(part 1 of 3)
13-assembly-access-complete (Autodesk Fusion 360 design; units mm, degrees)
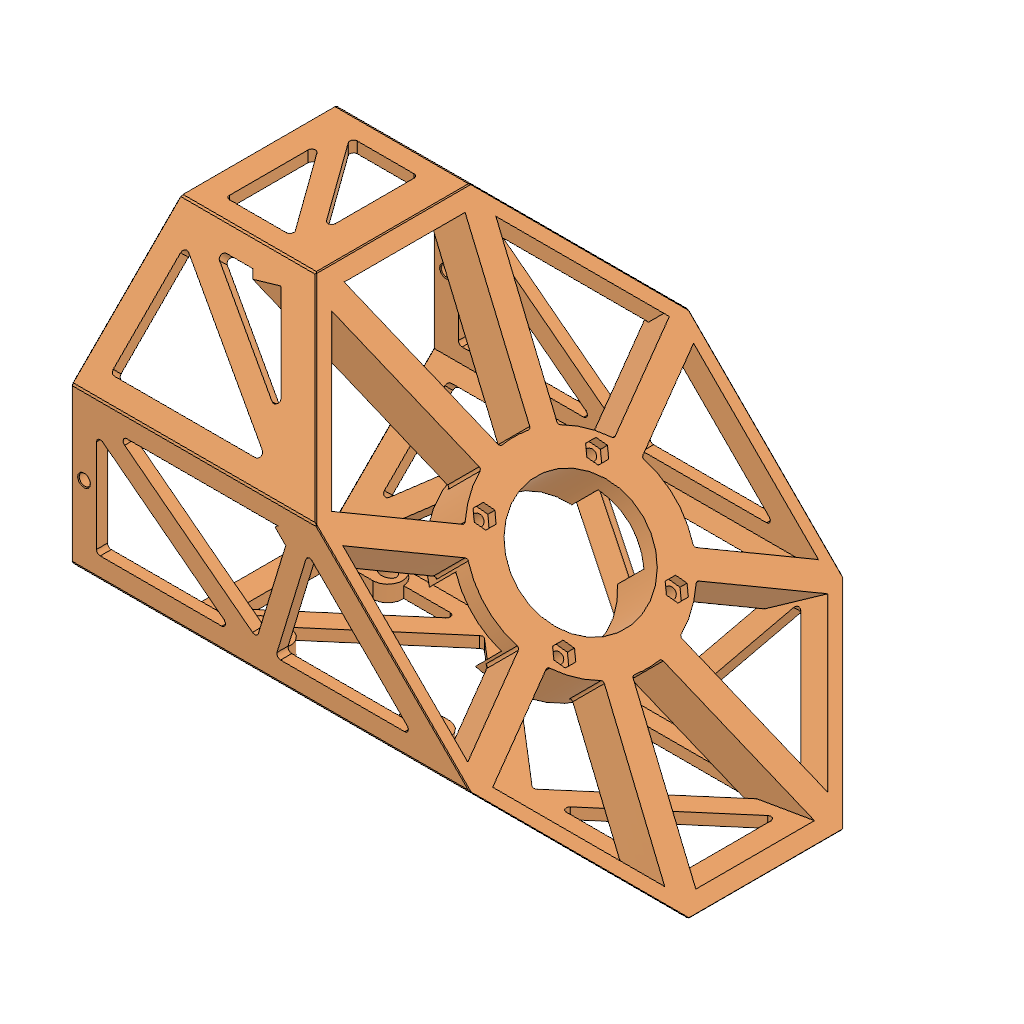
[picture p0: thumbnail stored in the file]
part number: 2026-11-02-20-17-55-344
part number: 2026-11-02-20-17-59-218
part number: 2026-11-02-20-17-59-224
part number: 2026-11-02-20-19-00-695
part number: 2026-11-02-20-19-03-009
part number: 2026-11-02-20-19-04-949
part number: 2026-11-02-20-19-06-912
part number: 2026-11-02-20-19-11-903
part number: 2026-11-02-20-19-12-666
part number: 2026-11-02-20-19-12-978
part number: 2026-11-02-20-19-13-740
part number: 2026-11-02-20-19-14-532
part number: 2026-11-02-20-19-15-361
part number: 2026-11-02-20-19-17-468
part number: 2026-11-02-20-19-19-583
part number: 2026-11-02-20-19-25-638
part number: 2026-11-02-20-19-39-091
parameter "bodyWidth" = 150 comment "Regular octagon across flats; corner diameter is larger."
parameter "bodyLength" = 260 comment "Overall straight length of the shared master blank."
parameter "splitAngle" = 45 comment "Keep this lesson angle at45 degrees."
parameter "faceGap" = 1 comment "Gap between the two printed joint faces."
parameter "wall" = 4.5 comment "Integrated shell and side brace radial thickness."
parameter "faceHalfWidth" = 31.066 (= "bodyWidth * ( sqrt(2) - 1 ) / 2") comment "Half-width of each outer planar facet."
parameter "memberWidth" = 8 comment "Nominal brace and corner chord width in a facet."
parameter "nodeHalfWidth" = 27.066 (= "faceHalfWidth - memberWidth / 2") comment "Chord centerlines measured from facet center."
parameter "jointNodeQ" = 7 comment "First truss skeleton row from the center joint plane."
parameter "endRim" = 10 comment "Uncut axial rim at each distant end."
parameter "endNodeX" = 124 (= "bodyLength / 2 - endRim + memberWidth / 2") comment "Last skeleton row before aperture inset."
parameter "apertureRadius" = 1.5 comment "Rounded internal corners at triangular openings."
parameter "spokeWidth" = 10 comment "Width of each deep bearing bulkhead spoke."
parameter "spokeDepth" = 18 comment "Bulkhead depth normal to the diagonal joint face."
parameter "carrierOD" = 52 comment "Outside of integrated A front bearing carrier."
parameter "rearCarrierClearance" = 46 comment "Internal carrier relief above front bearing shoulder."
parameter "tubeCornerChamfer" = 0.5 comment "Exposed outside octagon corner bevel."
parameter "tubeRimChamfer" = 0.3 comment "End rim and print-contact edge relief."
parameter "cordStation" = 125 (= "bodyLength / 2 - endRim / 2") comment "Load-test cord port center measured along body X."
parameter "bearingOD" = 22 comment "608 measured outside diameter."
parameter "bearingID" = 8 comment "608 bore."
parameter "bearingWidth" = 7 comment "608 width."
parameter "seatAllowance" = 0.2 comment "Trial DIAMETRAL clearance; choose with printed coupon."
parameter "seatDiameter" = 22.2 (= "bearingOD + seatAllowance") comment "Measured fit controls this."
parameter "coreOD" = 44 comment "Bearing holder outer diameter."
parameter "raceRelief" = 19.5 comment "Outer-ring shoulder opening; verify seals."
parameter "frontSeatDepth" = 7.1 comment "0.1 mm outer-ring axial allowance."
parameter "rearSeatDepth" = 7.2 comment "0.2 mm outer-ring axial float."
parameter "shoulder" = 3 comment "Backing behind each bearing seat."
parameter "supportSpacer" = 12 comment "Purchased metal M3 spacer length."
parameter "supportCircle" = 34 comment "Three M3 support bolts."
parameter "supportSpacerOD" = 6 comment "Purchased spacer outside diameter."
parameter "capThickness" = 3 comment "Both printed outer-ring retaining caps."
parameter "m3Clearance" = 3.3 comment "M3 through holes."
parameter "m4Clearance" = 4.3 comment "M4 through holes."
parameter "qFront" = 0.5 (= "faceGap / 2") comment "Front bearing starts at A mating face."
parameter "qFrontBack" = 10.6 (= "qFront + frontSeatDepth + shoulder") comment "End of integrated A holder."
parameter "qRearBase" = 22.6 (= "qFrontBack + supportSpacer") comment "Start of removable rear holder."
parameter "qRearBearing" = 25.6 (= "qRearBase + shoulder") comment "Rear bearing inner end."
parameter "qRearEnd" = 32.8 (= "qRearBearing + rearSeatDepth") comment "Rear holder outer end."
parameter "bearingSpacing" = 25.1 (= "qRearBearing - qFront") comment "Derived support-center spacing, not a bearing rating."
parameter "mountOD" = 76 comment "B mount and F flange outside diameter."
parameter "mountCircle" = 64 comment "Four M4 attachment holes."
parameter "mountOpening" = 50.3 comment "B through opening."
parameter "hubFace" = -23 comment "Metal hub flat mounting face."
parameter "adapterThickness" = 6 comment "F flange and metal compression sleeve length."
parameter "pilotDiameter" = 50 comment "F shallow centering pilot."
parameter "pilotInside" = 34 comment "Clearance around metal hub."
parameter "pilotHeight" = 2 comment "Short pilot only."
parameter "hubHoleSpacing" = 16 comment "Metal Sonic hub square hole spacing."
parameter "sleeveOD" = 8 comment "M4 metal compression sleeves."
parameter "sleeveAllowance" = 0.2 comment "Trial DIAMETRAL sleeve clearance."
parameter "shaftClearance" = 8.5 comment "F clearance hole; not a bearing."
parameter "nutAF" = 7.2 comment "M4 nominal 7 AF nut trial pocket."
parameter "nutDepth" = 4 comment "Open front M4 nut pocket."
parameter "rootRadius" = 1 comment "Hub-to-wall blend."
parameter "entryChamfer" = 0.4 comment "Assembly lead-in."
parameter "bedRelief" = 0.3 comment "Bed-contact edge allowance."
parameter "driverPort" = 5 comment "Clearance for bare3 mm hex-key shafts; bulky bit holders do not fit."
parameter "accessPadWidth" = 12 comment "Reinforced access-port capsule width."
parameter "accessPadExtra" = 2 comment "Local inward reinforcement beyond nominal side wall."
sketch "01 Master Octagon" plane through (0, 0, 0) normal (1, 0, 0) x axis (0, 0, -1)
  line L1 (31.066, 75) -> (75, 31.066)
  line L2 (-31.066, 75) -> (31.066, 75)
  line L3 (-75, 31.066) -> (-31.066, 75)
  line L4 (-75, -31.066) -> (-75, 31.066)
  line L5 (-31.066, -75) -> (-75, -31.066)
  line L6 (31.066, -75) -> (-31.066, -75)
  line L7 (75, -31.066) -> (31.066, -75)
  line L8 (75, 31.066) -> (75, -31.066)
  point P1 (0, 0)
  point P10 (0, 0)
  point P3 (31.066, 75)
  point P8 (31.066, -75)
  coincident P1 P10
  horizontal L2
  dimension "d59" distance P3 P8 = 150 (= "bodyWidth")
extrude "Extrude1" new body sketch "01 Master Octagon" distance 260 (= "bodyLength")
work_plane "WorkPlane1" RotateAngle 45 (= "splitAngle") ExtraOffset 0
split "Split1"
offset_faces "OffsetFaces1" distance -0.5 (= "-faceGap / 2")
offset_faces "OffsetFaces2" distance -0.5 (= "-faceGap / 2")
component_from_bodies "Body->Comp1"
component_from_bodies "Body->Comp2"
shell "Shell1" innerThickness 4.5 (= "wall")
shell "Shell1" innerThickness 4.5 (= "wall")
work_plane "WorkPlane1" RotateAngle -90 ExtraOffset 0
work_plane "WorkPlane2" AlongDistance 75 (= "bodyWidth / 2") ExtraOffset 0
sketch "A Facet 0 Triangle 1" plane through (0, 75, 0) normal (0, 1, 0) x axis (1, 0, 0)
  line L1 (-65.1005, -27.066) -> (-65.1005, 27.066)
  line L2 (60.9665, 27.066) -> (-65.1005, -27.066)
  line L3 (-65.1005, 27.066) -> (60.9665, 27.066)
  line L4 (-61.1005, -20.9953) -> (-61.1005, 23.066)
  line L5 (41.513, 23.066) -> (-61.1005, -20.9953)
  line L6 (-61.1005, 23.066) -> (41.513, 23.066)
  point P1 (0, 0)
  point P2 (-65.1005, 27.066)
  point P3 (-65.1005, -27.066)
  point P4 (60.9665, 27.066)
  dimension "d72" distance P1 P2 = 65.1005 (= "Linear Dimension-2")
  dimension "d73" distance P1 P2 = 27.066 (= "Linear Dimension-3")
  dimension "d74" distance P1 P3 = 65.1005 (= "Linear Dimension-4")
  dimension "d75" distance P1 P3 = 27.066 (= "Linear Dimension-5")
  dimension "d76" distance P1 P4 = 60.9665 (= "Linear Dimension-6")
  dimension "d77" distance P1 P4 = 27.066 (= "Linear Dimension-7")
  dimension "d78" = -4 (= "-memberWidth / 2")
extrude "Extrude1" cut sketch "A Facet 0 Triangle 1" profile of L5 L6 L4 against normal blind 4.7 (magnitude of "-( wall + 0.2 mm )")
sketch "A Facet 0 Triangle 2" plane through (0, 75, 0) normal (0, 1, 0) x axis (1, 0, 0)
  line L1 (60.9665, 27.066) -> (-65.1005, -27.066)
  line L2 (92.4832, -27.066) -> (60.9665, 27.066)
  line L3 (-65.1005, -27.066) -> (92.4832, -27.066)
  line L4 (59.2912, 21.9935) -> (-45.647, -23.066)
  line L5 (85.5258, -23.066) -> (59.2912, 21.9935)
  line L6 (-45.647, -23.066) -> (85.5258, -23.066)
  point P1 (0, 0)
  point P2 (-65.1005, -27.066)
  point P3 (60.9665, 27.066)
  point P4 (92.4832, -27.066)
  dimension "d81" distance P1 P2 = 65.1005 (= "Linear Dimension-2")
  dimension "d82" distance P1 P2 = 27.066 (= "Linear Dimension-3")
  dimension "d83" distance P1 P3 = 60.9665 (= "Linear Dimension-4")
  dimension "d84" distance P1 P3 = 27.066 (= "Linear Dimension-5")
  dimension "d85" distance P1 P4 = 92.4832 (= "Linear Dimension-6")
  dimension "d86" distance P1 P4 = 27.066 (= "Linear Dimension-7")
  dimension "d87" = 4 (= "memberWidth / 2")
extrude "Extrude2" cut sketch "A Facet 0 Triangle 2" profile of L5 L6 L4 against normal blind 4.7 (magnitude of "-( wall + 0.2 mm )")
sketch "A Facet 0 Triangle 3" plane through (0, 75, 0) normal (0, 1, 0) x axis (1, 0, 0)
  line L1 (92.4832, -27.066) -> (60.9665, 27.066)
  line L2 (124, 27.066) -> (92.4832, -27.066)
  line L3 (60.9665, 27.066) -> (124, 27.066)
  line L4 (92.4832, -19.1161) -> (67.924, 23.066)
  line L5 (117.0425, 23.066) -> (92.4832, -19.1161)
  line L6 (67.924, 23.066) -> (117.0425, 23.066)
  point P1 (0, 0)
  point P2 (60.9665, 27.066)
  point P3 (92.4832, -27.066)
  point P4 (124, 27.066)
  dimension "d90" distance P1 P2 = 60.9665 (= "Linear Dimension-2")
  dimension "d91" distance P1 P2 = 27.066 (= "Linear Dimension-3")
  dimension "d92" distance P1 P3 = 92.4832 (= "Linear Dimension-4")
  dimension "d93" distance P1 P3 = 27.066 (= "Linear Dimension-5")
  dimension "d94" distance P1 P4 = 124 (= "Linear Dimension-6")
  dimension "d95" distance P1 P4 = 27.066 (= "Linear Dimension-7")
  dimension "d96" = -4 (= "-memberWidth / 2")
extrude "Extrude3" cut sketch "A Facet 0 Triangle 3" profile of L5 L6 L4 against normal blind 4.7 (magnitude of "-( wall + 0.2 mm )")
sketch "A Facet 0 Triangle 4" plane through (0, 75, 0) normal (0, 1, 0) x axis (1, 0, 0)
  line L1 (124, 27.066) -> (92.4832, -27.066)
  line L2 (124, -27.066) -> (124, 27.066)
  line L3 (92.4832, -27.066) -> (124, -27.066)
  line L4 (120, 12.2459) -> (99.4407, -23.066)
  line L5 (120, -23.066) -> (120, 12.2459)
  line L6 (99.4407, -23.066) -> (120, -23.066)
  point P1 (0, 0)
  point P2 (92.4832, -27.066)
  point P3 (124, 27.066)
  point P4 (124, -27.066)
  dimension "d99" distance P1 P2 = 92.4832 (= "Linear Dimension-2")
  dimension "d100" distance P1 P2 = 27.066 (= "Linear Dimension-3")
  dimension "d101" distance P1 P3 = 124 (= "Linear Dimension-4")
  dimension "d102" distance P1 P3 = 27.066 (= "Linear Dimension-5")
  dimension "d103" distance P1 P4 = 124 (= "Linear Dimension-6")
  dimension "d104" distance P1 P4 = 27.066 (= "Linear Dimension-7")
  dimension "d105" = 4 (= "memberWidth / 2")
extrude "Extrude4" cut sketch "A Facet 0 Triangle 4" profile of L5 L6 L4 against normal blind 4.7 (magnitude of "-( wall + 0.2 mm )")
fillet "Fillet1" radius 1.5 (= "apertureRadius")
work_plane "WorkPlane3" RotateAngle -45 ExtraOffset 0
work_plane "WorkPlane4" AlongDistance 75 (= "bodyWidth / 2") ExtraOffset 0
sketch "A Facet 45 Triangle 1" plane through (0, 53.033, 53.033) normal (0, 0.7071, 0.7071) x axis (1, 0, 0)
  line L1 (-23.9949, -27.066) -> (-62.2721, 27.066)
  line L2 (-0.1814, 27.066) -> (-23.9949, -27.066)
  line L3 (-62.2721, 27.066) -> (-0.1814, 27.066)
  line L4 (-24.81, -18.9852) -> (-54.5447, 23.066)
  line L5 (-6.311, 23.066) -> (-24.81, -18.9852)
  line L6 (-54.5447, 23.066) -> (-6.311, 23.066)
  point P1 (0, 0)
  point P2 (-62.2721, 27.066)
  point P3 (-23.9949, -27.066)
  point P4 (-0.1814, 27.066)
  dimension "d114" distance P1 P2 = 62.2721 (= "Linear Dimension-2")
  dimension "d115" distance P1 P2 = 27.066 (= "Linear Dimension-3")
  dimension "d116" distance P1 P3 = 23.9949 (= "Linear Dimension-4")
  dimension "d117" distance P1 P3 = 27.066 (= "Linear Dimension-5")
  dimension "d118" distance P1 P4 = 0.1814 (= "Linear Dimension-6")
  dimension "d119" distance P1 P4 = 27.066 (= "Linear Dimension-7")
  dimension "d120" = -4 (= "-memberWidth / 2")
extrude "Extrude5" cut sketch "A Facet 45 Triangle 1" profile of L5 L6 L4 against normal blind 4.7 (magnitude of "-( wall + 0.2 mm )")
sketch "A Facet 45 Triangle 2" plane through (0, 53.033, 53.033) normal (0, 0.7071, 0.7071) x axis (1, 0, 0)
  line L1 (-0.1814, 27.066) -> (-23.9949, -27.066)
  line L2 (74.6684, -27.066) -> (-0.1814, 27.066)
  line L3 (-23.9949, -27.066) -> (74.6684, -27.066)
  line L4 (1.4863, 20.9235) -> (-17.8653, -23.066)
  line L5 (62.3117, -23.066) -> (1.4863, 20.9235)
  line L6 (-17.8653, -23.066) -> (62.3117, -23.066)
  point P1 (0, 0)
  point P2 (-23.9949, -27.066)
  point P3 (-0.1814, 27.066)
  point P4 (74.6684, -27.066)
  dimension "d123" distance P1 P2 = 23.9949 (= "Linear Dimension-2")
  dimension "d124" distance P1 P2 = 27.066 (= "Linear Dimension-3")
  dimension "d125" distance P1 P3 = 0.1814 (= "Linear Dimension-4")
  dimension "d126" distance P1 P3 = 27.066 (= "Linear Dimension-5")
  dimension "d127" distance P1 P4 = 74.6684 (= "Linear Dimension-6")
  dimension "d128" distance P1 P4 = 27.066 (= "Linear Dimension-7")
  dimension "d129" = 4 (= "memberWidth / 2")
extrude "Extrude6" cut sketch "A Facet 45 Triangle 2" profile of L5 L6 L4 against normal blind 4.7 (magnitude of "-( wall + 0.2 mm )")
sketch "A Facet 45 Triangle 3" plane through (0, 53.033, 53.033) normal (0, 0.7071, 0.7071) x axis (1, 0, 0)
  line L1 (74.6684, -27.066) -> (-0.1814, 27.066)
  line L2 (124, 27.066) -> (74.6684, -27.066)
  line L3 (-0.1814, 27.066) -> (124, 27.066)
  line L4 (74.1179, -21.7315) -> (12.1753, 23.066)
  line L5 (114.9429, 23.066) -> (74.1179, -21.7315)
  line L6 (12.1753, 23.066) -> (114.9429, 23.066)
  point P1 (0, 0)
  point P2 (-0.1814, 27.066)
  point P3 (74.6684, -27.066)
  point P4 (124, 27.066)
  dimension "d132" distance P1 P2 = 0.1814 (= "Linear Dimension-2")
  dimension "d133" distance P1 P2 = 27.066 (= "Linear Dimension-3")
  dimension "d134" distance P1 P3 = 74.6684 (= "Linear Dimension-4")
  dimension "d135" distance P1 P3 = 27.066 (= "Linear Dimension-5")
  dimension "d136" distance P1 P4 = 124 (= "Linear Dimension-6")
  dimension "d137" distance P1 P4 = 27.066 (= "Linear Dimension-7")
  dimension "d138" = -4 (= "-memberWidth / 2")
extrude "Extrude7" cut sketch "A Facet 45 Triangle 3" profile of L5 L6 L4 against normal blind 4.7 (magnitude of "-( wall + 0.2 mm )")
sketch "A Facet 45 Triangle 4" plane through (0, 53.033, 53.033) normal (0, 0.7071, 0.7071) x axis (1, 0, 0)
  line L1 (124, 27.066) -> (74.6684, -27.066)
  line L2 (124, -27.066) -> (124, 27.066)
  line L3 (74.6684, -27.066) -> (124, -27.066)
  line L4 (120, 16.7383) -> (83.7255, -23.066)
  line L5 (120, -23.066) -> (120, 16.7383)
  line L6 (83.7255, -23.066) -> (120, -23.066)
  point P1 (0, 0)
  point P2 (74.6684, -27.066)
  point P3 (124, 27.066)
  point P4 (124, -27.066)
  dimension "d141" distance P1 P2 = 74.6684 (= "Linear Dimension-2")
  dimension "d142" distance P1 P2 = 27.066 (= "Linear Dimension-3")
  dimension "d143" distance P1 P3 = 124 (= "Linear Dimension-4")
  dimension "d144" distance P1 P3 = 27.066 (= "Linear Dimension-5")
  dimension "d145" distance P1 P4 = 124 (= "Linear Dimension-6")
  dimension "d146" distance P1 P4 = 27.066 (= "Linear Dimension-7")
  dimension "d147" = 4 (= "memberWidth / 2")
extrude "Extrude8" cut sketch "A Facet 45 Triangle 4" profile of L5 L6 L4 against normal blind 4.7 (magnitude of "-( wall + 0.2 mm )")
fillet "Fillet2" radius 1.5 (= "apertureRadius")
work_plane "WorkPlane5" RotateAngle 0 ExtraOffset 0
work_plane "WorkPlane6" AlongDistance 75 (= "bodyWidth / 2") ExtraOffset 0
sketch "A Facet 90 Triangle 1" plane through (0, 0, 75) normal (0, 0, 1) x axis (1, 0, 0)
  line L1 (36.9655, -27.066) -> (-17.1665, 27.066)
  line L2 (53.4167, 27.066) -> (36.9655, -27.066)
  line L3 (-17.1665, 27.066) -> (53.4167, 27.066)
  line L4 (35.0777, -19.5214) -> (-7.5097, 23.066)
  line L5 (48.0205, 23.066) -> (35.0777, -19.5214)
  line L6 (-7.5097, 23.066) -> (48.0205, 23.066)
  point P1 (0, 0)
  point P2 (-17.1665, 27.066)
  point P3 (36.9655, -27.066)
  point P4 (53.4167, 27.066)
  dimension "d156" distance P1 P2 = 17.1665 (= "Linear Dimension-2")
  dimension "d157" distance P1 P2 = 27.066 (= "Linear Dimension-3")
  dimension "d158" distance P1 P3 = 36.9655 (= "Linear Dimension-4")
  dimension "d159" distance P1 P3 = 27.066 (= "Linear Dimension-5")
  dimension "d160" distance P1 P4 = 53.4167 (= "Linear Dimension-6")
  dimension "d161" distance P1 P4 = 27.066 (= "Linear Dimension-7")
  dimension "d162" = -4 (= "-memberWidth / 2")
extrude "Extrude9" cut sketch "A Facet 90 Triangle 1" profile of L5 L6 L4 against normal blind 4.7 (magnitude of "-( wall + 0.2 mm )")
sketch "A Facet 90 Triangle 2" plane through (0, 0, 75) normal (0, 0, 1) x axis (1, 0, 0)
  line L1 (53.4167, 27.066) -> (36.9655, -27.066)
  line L2 (124, -27.066) -> (53.4167, 27.066)
  line L3 (36.9655, -27.066) -> (124, -27.066)
  line L4 (55.5648, 20.3777) -> (42.3618, -23.066)
  line L5 (112.2115, -23.066) -> (55.5648, 20.3777)
  line L6 (42.3618, -23.066) -> (112.2115, -23.066)
  point P1 (0, 0)
  point P2 (36.9655, -27.066)
  point P3 (53.4167, 27.066)
  point P4 (124, -27.066)
  dimension "d165" distance P1 P2 = 36.9655 (= "Linear Dimension-2")
  dimension "d166" distance P1 P2 = 27.066 (= "Linear Dimension-3")
  dimension "d167" distance P1 P3 = 53.4167 (= "Linear Dimension-4")
  dimension "d168" distance P1 P3 = 27.066 (= "Linear Dimension-5")
  dimension "d169" distance P1 P4 = 124 (= "Linear Dimension-6")
  dimension "d170" distance P1 P4 = 27.066 (= "Linear Dimension-7")
  dimension "d171" = 4 (= "memberWidth / 2")
extrude "Extrude10" cut sketch "A Facet 90 Triangle 2" profile of L5 L6 L4 against normal blind 4.7 (magnitude of "-( wall + 0.2 mm )")
sketch "A Facet 90 Triangle 3" plane through (0, 0, 75) normal (0, 0, 1) x axis (1, 0, 0)
  line L1 (124, -27.066) -> (53.4167, 27.066)
  line L2 (124, 27.066) -> (124, -27.066)
  line L3 (53.4167, 27.066) -> (124, 27.066)
  line L4 (120, -18.9574) -> (65.2053, 23.066)
  line L5 (120, 23.066) -> (120, -18.9574)
  line L6 (65.2053, 23.066) -> (120, 23.066)
  point P1 (0, 0)
  point P2 (53.4167, 27.066)
  point P3 (124, -27.066)
  point P4 (124, 27.066)
  dimension "d174" distance P1 P2 = 53.4167 (= "Linear Dimension-2")
  dimension "d175" distance P1 P2 = 27.066 (= "Linear Dimension-3")
  dimension "d176" distance P1 P3 = 124 (= "Linear Dimension-4")
  dimension "d177" distance P1 P3 = 27.066 (= "Linear Dimension-5")
  dimension "d178" distance P1 P4 = 124 (= "Linear Dimension-6")
  dimension "d179" distance P1 P4 = 27.066 (= "Linear Dimension-7")
  dimension "d180" = -4 (= "-memberWidth / 2")
extrude "Extrude11" cut sketch "A Facet 90 Triangle 3" profile of L5 L6 L4 against normal blind 4.7 (magnitude of "-( wall + 0.2 mm )")
fillet "Fillet3" radius 1.5 (= "apertureRadius")
work_plane "WorkPlane7" RotateAngle 45 ExtraOffset 0
work_plane "WorkPlane8" AlongDistance 75 (= "bodyWidth / 2") ExtraOffset 0
sketch "A Facet 135 Triangle 1" plane through (0, -53.033, 53.033) normal (0, -0.7071, 0.7071) x axis (1, 0, 0)
  line L1 (82.0711, -27.066) -> (43.7939, 27.066)
  line L2 (124, 27.066) -> (82.0711, -27.066)
  line L3 (43.7939, 27.066) -> (124, 27.066)
  line L4 (82.2175, -20.3449) -> (51.5213, 23.066)
  line L5 (115.8422, 23.066) -> (82.2175, -20.3449)
  line L6 (51.5213, 23.066) -> (115.8422, 23.066)
  point P1 (0, 0)
  point P2 (43.7939, 27.066)
  point P3 (82.0711, -27.066)
  point P4 (124, 27.066)
  dimension "d189" distance P1 P2 = 43.7939 (= "Linear Dimension-2")
  dimension "d190" distance P1 P2 = 27.066 (= "Linear Dimension-3")
  dimension "d191" distance P1 P3 = 82.0711 (= "Linear Dimension-4")
  dimension "d192" distance P1 P3 = 27.066 (= "Linear Dimension-5")
  dimension "d193" distance P1 P4 = 124 (= "Linear Dimension-6")
  dimension "d194" distance P1 P4 = 27.066 (= "Linear Dimension-7")
  dimension "d195" = -4 (= "-memberWidth / 2")
extrude "Extrude12" cut sketch "A Facet 135 Triangle 1" profile of L5 L6 L4 against normal blind 4.7 (magnitude of "-( wall + 0.2 mm )")
sketch "A Facet 135 Triangle 2" plane through (0, -53.033, 53.033) normal (0, -0.7071, 0.7071) x axis (1, 0, 0)
  line L1 (124, 27.066) -> (82.0711, -27.066)
  line L2 (124, -27.066) -> (124, 27.066)
  line L3 (82.0711, -27.066) -> (124, -27.066)
  line L4 (120, 15.3697) -> (90.2289, -23.066)
  line L5 (120, -23.066) -> (120, 15.3697)
  line L6 (90.2289, -23.066) -> (120, -23.066)
  point P1 (0, 0)
  point P2 (82.0711, -27.066)
  point P3 (124, 27.066)
  point P4 (124, -27.066)
  dimension "d198" distance P1 P2 = 82.0711 (= "Linear Dimension-2")
  dimension "d199" distance P1 P2 = 27.066 (= "Linear Dimension-3")
  dimension "d200" distance P1 P3 = 124 (= "Linear Dimension-4")
  dimension "d201" distance P1 P3 = 27.066 (= "Linear Dimension-5")
  dimension "d202" distance P1 P4 = 124 (= "Linear Dimension-6")
  dimension "d203" distance P1 P4 = 27.066 (= "Linear Dimension-7")
  dimension "d204" = 4 (= "memberWidth / 2")
extrude "Extrude13" cut sketch "A Facet 135 Triangle 2" profile of L5 L6 L4 against normal blind 4.7 (magnitude of "-( wall + 0.2 mm )")
fillet "Fillet4" radius 1.5 (= "apertureRadius")
work_plane "WorkPlane9" RotateAngle 90 ExtraOffset 0
work_plane "WorkPlane10" AlongDistance 75 (= "bodyWidth / 2") ExtraOffset 0
sketch "A Facet 180 Triangle 1" plane through (0, -75, 0) normal (0, -1, 0) x axis (-1, 0, 0)
  line L1 (-84.8995, 27.066) -> (-84.8995, -27.066)
  line L2 (-124, -27.066) -> (-84.8995, 27.066)
  line L3 (-84.8995, -27.066) -> (-124, -27.066)
  line L4 (-88.8995, 14.697) -> (-88.8995, -23.066)
  line L5 (-116.1764, -23.066) -> (-88.8995, 14.697)
  line L6 (-88.8995, -23.066) -> (-116.1764, -23.066)
  point P1 (0, 0)
  point P2 (-84.8995, -27.066)
  point P3 (-84.8995, 27.066)
  point P4 (-124, -27.066)
  dimension "d213" distance P1 P2 = 84.8995 (= "Linear Dimension-2")
  dimension "d214" distance P1 P2 = 27.066 (= "Linear Dimension-3")
  dimension "d215" distance P1 P3 = 84.8995 (= "Linear Dimension-4")
  dimension "d216" distance P1 P3 = 27.066 (= "Linear Dimension-5")
  dimension "d217" distance P1 P4 = 124 (= "Linear Dimension-6")
  dimension "d218" distance P1 P4 = 27.066 (= "Linear Dimension-7")
  dimension "d219" = -4 (= "-memberWidth / 2")
extrude "Extrude14" cut sketch "A Facet 180 Triangle 1" profile of L5 L6 L4 against normal blind 4.7 (magnitude of "-( wall + 0.2 mm )")
sketch "A Facet 180 Triangle 2" plane through (0, -75, 0) normal (0, -1, 0) x axis (-1, 0, 0)
  line L1 (-124, -27.066) -> (-84.8995, 27.066)
  line L2 (-124, 27.066) -> (-124, -27.066)
  line L3 (-84.8995, 27.066) -> (-124, 27.066)
  line L4 (-120, -14.697) -> (-92.7231, 23.066)
  line L5 (-120, 23.066) -> (-120, -14.697)
  line L6 (-92.7231, 23.066) -> (-120, 23.066)
  point P1 (0, 0)
  point P2 (-84.8995, 27.066)
  point P3 (-124, -27.066)
  point P4 (-124, 27.066)
  dimension "d222" distance P1 P2 = 84.8995 (= "Linear Dimension-2")
  dimension "d223" distance P1 P2 = 27.066 (= "Linear Dimension-3")
  dimension "d224" distance P1 P3 = 124 (= "Linear Dimension-4")
  dimension "d225" distance P1 P3 = 27.066 (= "Linear Dimension-5")
  dimension "d226" distance P1 P4 = 124 (= "Linear Dimension-6")
  dimension "d227" distance P1 P4 = 27.066 (= "Linear Dimension-7")
  dimension "d228" = 4 (= "memberWidth / 2")
extrude "Extrude15" cut sketch "A Facet 180 Triangle 2" profile of L5 L6 L4 against normal blind 4.7 (magnitude of "-( wall + 0.2 mm )")
fillet "Fillet5" radius 1.5 (= "apertureRadius")
work_plane "WorkPlane11" RotateAngle 135 ExtraOffset 0
work_plane "WorkPlane12" AlongDistance 75 (= "bodyWidth / 2") ExtraOffset 0
sketch "A Facet 225 Triangle 1" plane through (0, -53.033, -53.033) normal (0, -0.7071, -0.7071) x axis (1, 0, 0)
  line L1 (43.7939, -27.066) -> (82.0711, 27.066)
  line L2 (124, 27.066) -> (43.7939, -27.066)
  line L3 (82.0711, 27.066) -> (124, 27.066)
  line L4 (59.6927, -11.51) -> (84.1416, 23.066)
  line L5 (110.9231, 23.066) -> (59.6927, -11.51)
  line L6 (84.1416, 23.066) -> (110.9231, 23.066)
  point P1 (0, 0)
  point P2 (82.0711, 27.066)
  point P3 (43.7939, -27.066)
  point P4 (124, 27.066)
  dimension "d237" distance P1 P2 = 82.0711 (= "Linear Dimension-2")
  dimension "d238" distance P1 P2 = 27.066 (= "Linear Dimension-3")
  dimension "d239" distance P1 P3 = 43.7939 (= "Linear Dimension-4")
  dimension "d240" distance P1 P3 = 27.066 (= "Linear Dimension-5")
  dimension "d241" distance P1 P4 = 124 (= "Linear Dimension-6")
  dimension "d242" distance P1 P4 = 27.066 (= "Linear Dimension-7")
  dimension "d243" = -4 (= "-memberWidth / 2")
extrude "Extrude16" cut sketch "A Facet 225 Triangle 1" profile of L5 L6 L4 against normal blind 4.7 (magnitude of "-( wall + 0.2 mm )")
sketch "A Facet 225 Triangle 2" plane through (0, -53.033, -53.033) normal (0, -0.7071, -0.7071) x axis (1, 0, 0)
  line L1 (124, 27.066) -> (43.7939, -27.066)
  line L2 (124, -27.066) -> (124, 27.066)
  line L3 (43.7939, -27.066) -> (124, -27.066)
  line L4 (120, 19.5406) -> (56.8709, -23.066)
  line L5 (120, -23.066) -> (120, 19.5406)
  line L6 (56.8709, -23.066) -> (120, -23.066)
  point P1 (0, 0)
  point P2 (43.7939, -27.066)
  point P3 (124, 27.066)
  point P4 (124, -27.066)
  dimension "d246" distance P1 P2 = 43.7939 (= "Linear Dimension-2")
  dimension "d247" distance P1 P2 = 27.066 (= "Linear Dimension-3")
  dimension "d248" distance P1 P3 = 124 (= "Linear Dimension-4")
  dimension "d249" distance P1 P3 = 27.066 (= "Linear Dimension-5")
  dimension "d250" distance P1 P4 = 124 (= "Linear Dimension-6")
  dimension "d251" distance P1 P4 = 27.066 (= "Linear Dimension-7")
  dimension "d252" = 4 (= "memberWidth / 2")
extrude "Extrude17" cut sketch "A Facet 225 Triangle 2" profile of L5 L6 L4 against normal blind 4.7 (magnitude of "-( wall + 0.2 mm )")
fillet "Fillet6" radius 1.5 (= "apertureRadius")
work_plane "WorkPlane13" RotateAngle 180 ExtraOffset 0
work_plane "WorkPlane14" AlongDistance 75 (= "bodyWidth / 2") ExtraOffset 0
sketch "A Facet 270 Triangle 1" plane through (0, 0, -75) normal (0, 0, -1) x axis (-1, 0, 0)
  line L1 (17.1665, 27.066) -> (-36.9655, -27.066)
  line L2 (-80.4828, -27.066) -> (17.1665, 27.066)
  line L3 (-36.9655, -27.066) -> (-80.4828, -27.066)
  line L4 (-5.7896, 9.7668) -> (-38.6224, -23.066)
  line L5 (-65.0169, -23.066) -> (-5.7896, 9.7668)
  line L6 (-38.6224, -23.066) -> (-65.0169, -23.066)
  point P1 (0, 0)
  point P2 (-36.9655, -27.066)
  point P3 (17.1665, 27.066)
  point P4 (-80.4828, -27.066)
  dimension "d261" distance P1 P2 = 36.9655 (= "Linear Dimension-2")
  dimension "d262" distance P1 P2 = 27.066 (= "Linear Dimension-3")
  dimension "d263" distance P1 P3 = 17.1665 (= "Linear Dimension-4")
  dimension "d264" distance P1 P3 = 27.066 (= "Linear Dimension-5")
  dimension "d265" distance P1 P4 = 80.4828 (= "Linear Dimension-6")
  dimension "d266" distance P1 P4 = 27.066 (= "Linear Dimension-7")
  dimension "d267" = -4 (= "-memberWidth / 2")
extrude "Extrude18" cut sketch "A Facet 270 Triangle 1" profile of L5 L6 L4 against normal blind 4.7 (magnitude of "-( wall + 0.2 mm )")
sketch "A Facet 270 Triangle 2" plane through (0, 0, -75) normal (0, 0, -1) x axis (-1, 0, 0)
  line L1 (-80.4828, -27.066) -> (17.1665, 27.066)
  line L2 (-124, 27.066) -> (-80.4828, -27.066)
  line L3 (17.1665, 27.066) -> (-124, 27.066)
  line L4 (-79.4759, -21.9343) -> (1.7007, 23.066)
  line L5 (-115.6521, 23.066) -> (-79.4759, -21.9343)
  line L6 (1.7007, 23.066) -> (-115.6521, 23.066)
  point P1 (0, 0)
  point P2 (17.1665, 27.066)
  point P3 (-80.4828, -27.066)
  point P4 (-124, 27.066)
  dimension "d270" distance P1 P2 = 17.1665 (= "Linear Dimension-2")
  dimension "d271" distance P1 P2 = 27.066 (= "Linear Dimension-3")
  dimension "d272" distance P1 P3 = 80.4828 (= "Linear Dimension-4")
  dimension "d273" distance P1 P3 = 27.066 (= "Linear Dimension-5")
  dimension "d274" distance P1 P4 = 124 (= "Linear Dimension-6")
  dimension "d275" distance P1 P4 = 27.066 (= "Linear Dimension-7")
  dimension "d276" = 4 (= "memberWidth / 2")
extrude "Extrude19" cut sketch "A Facet 270 Triangle 2" profile of L5 L6 L4 against normal blind 4.7 (magnitude of "-( wall + 0.2 mm )")
sketch "A Facet 270 Triangle 3" plane through (0, 0, -75) normal (0, 0, -1) x axis (-1, 0, 0)
  line L1 (-124, 27.066) -> (-80.4828, -27.066)
  line L2 (-124, -27.066) -> (-124, 27.066)
  line L3 (-80.4828, -27.066) -> (-124, -27.066)
  line L4 (-120, 15.7062) -> (-88.8307, -23.066)
  line L5 (-120, -23.066) -> (-120, 15.7062)
  line L6 (-88.8307, -23.066) -> (-120, -23.066)
  point P1 (0, 0)
  point P2 (-80.4828, -27.066)
  point P3 (-124, 27.066)
  point P4 (-124, -27.066)
  dimension "d279" distance P1 P2 = 80.4828 (= "Linear Dimension-2")
  dimension "d280" distance P1 P2 = 27.066 (= "Linear Dimension-3")
  dimension "d281" distance P1 P3 = 124 (= "Linear Dimension-4")
  dimension "d282" distance P1 P3 = 27.066 (= "Linear Dimension-5")
  dimension "d283" distance P1 P4 = 124 (= "Linear Dimension-6")
  dimension "d284" distance P1 P4 = 27.066 (= "Linear Dimension-7")
  dimension "d285" = -4 (= "-memberWidth / 2")
extrude "Extrude20" cut sketch "A Facet 270 Triangle 3" profile of L5 L6 L4 against normal blind 4.7 (magnitude of "-( wall + 0.2 mm )")
fillet "Fillet7" radius 1.5 (= "apertureRadius")
work_plane "WorkPlane15" RotateAngle 225 ExtraOffset 0
work_plane "WorkPlane16" AlongDistance 75 (= "bodyWidth / 2") ExtraOffset 0
sketch "A Facet 315 Triangle 1" plane through (0, 53.033, -53.033) normal (0, 0.7071, -0.7071) x axis (1, 0, 0)
  line L1 (-62.2721, -27.066) -> (-23.9949, 27.066)
  line L2 (25.3367, 27.066) -> (-62.2721, -27.066)
  line L3 (-23.9949, 27.066) -> (25.3367, 27.066)
  line L4 (-47.6674, -13.34) -> (-21.9244, 23.066)
  line L5 (11.2532, 23.066) -> (-47.6674, -13.34)
  line L6 (-21.9244, 23.066) -> (11.2532, 23.066)
  point P1 (0, 0)
  point P2 (-23.9949, 27.066)
  point P3 (-62.2721, -27.066)
  point P4 (25.3367, 27.066)
  dimension "d294" distance P1 P2 = 23.9949 (= "Linear Dimension-2")
  dimension "d295" distance P1 P2 = 27.066 (= "Linear Dimension-3")
  dimension "d296" distance P1 P3 = 62.2721 (= "Linear Dimension-4")
  dimension "d297" distance P1 P3 = 27.066 (= "Linear Dimension-5")
  dimension "d298" distance P1 P4 = 25.3367 (= "Linear Dimension-6")
  dimension "d299" distance P1 P4 = 27.066 (= "Linear Dimension-7")
  dimension "d300" = -4 (= "-memberWidth / 2")
extrude "Extrude21" cut sketch "A Facet 315 Triangle 1" profile of L5 L6 L4 against normal blind 4.7 (magnitude of "-( wall + 0.2 mm )")
sketch "A Facet 315 Triangle 2" plane through (0, 53.033, -53.033) normal (0, 0.7071, -0.7071) x axis (1, 0, 0)
  line L1 (25.3367, 27.066) -> (-62.2721, -27.066)
  line L2 (61.9093, -27.066) -> (25.3367, 27.066)
  line L3 (-62.2721, -27.066) -> (61.9093, -27.066)
  line L4 (24.1722, 21.6445) -> (-48.1886, -23.066)
  line L5 (54.3795, -23.066) -> (24.1722, 21.6445)
  line L6 (-48.1886, -23.066) -> (54.3795, -23.066)
  point P1 (0, 0)
  point P2 (-62.2721, -27.066)
  point P3 (25.3367, 27.066)
  point P4 (61.9093, -27.066)
  dimension "d303" distance P1 P2 = 62.2721 (= "Linear Dimension-2")
  dimension "d304" distance P1 P2 = 27.066 (= "Linear Dimension-3")
  dimension "d305" distance P1 P3 = 25.3367 (= "Linear Dimension-4")
  dimension "d306" distance P1 P3 = 27.066 (= "Linear Dimension-5")
  dimension "d307" distance P1 P4 = 61.9093 (= "Linear Dimension-6")
  dimension "d308" distance P1 P4 = 27.066 (= "Linear Dimension-7")
  dimension "d309" = 4 (= "memberWidth / 2")
extrude "Extrude22" cut sketch "A Facet 315 Triangle 2" profile of L5 L6 L4 against normal blind 4.7 (magnitude of "-( wall + 0.2 mm )")
sketch "A Facet 315 Triangle 3" plane through (0, 53.033, -53.033) normal (0, 0.7071, -0.7071) x axis (1, 0, 0)
  line L1 (61.9093, -27.066) -> (25.3367, 27.066)
  line L2 (124, 27.066) -> (61.9093, -27.066)
  line L3 (25.3367, 27.066) -> (124, 27.066)
  line L4 (62.6909, -21.0779) -> (32.8665, 23.066)
  line L5 (113.325, 23.066) -> (62.6909, -21.0779)
  line L6 (32.8665, 23.066) -> (113.325, 23.066)
  point P1 (0, 0)
  point P2 (25.3367, 27.066)
  point P3 (61.9093, -27.066)
  point P4 (124, 27.066)
  dimension "d312" distance P1 P2 = 25.3367 (= "Linear Dimension-2")
  dimension "d313" distance P1 P2 = 27.066 (= "Linear Dimension-3")
  dimension "d314" distance P1 P3 = 61.9093 (= "Linear Dimension-4")
  dimension "d315" distance P1 P3 = 27.066 (= "Linear Dimension-5")
  dimension "d316" distance P1 P4 = 124 (= "Linear Dimension-6")
  dimension "d317" distance P1 P4 = 27.066 (= "Linear Dimension-7")
  dimension "d318" = -4 (= "-memberWidth / 2")
extrude "Extrude23" cut sketch "A Facet 315 Triangle 3" profile of L5 L6 L4 against normal blind 4.7 (magnitude of "-( wall + 0.2 mm )")
sketch "A Facet 315 Triangle 4" plane through (0, 53.033, -53.033) normal (0, 0.7071, -0.7071) x axis (1, 0, 0)
  line L1 (124, 27.066) -> (61.9093, -27.066)
  line L2 (124, -27.066) -> (124, 27.066)
  line L3 (61.9093, -27.066) -> (124, -27.066)
  line L4 (120, 18.272) -> (72.5843, -23.066)
  line L5 (120, -23.066) -> (120, 18.272)
  line L6 (72.5843, -23.066) -> (120, -23.066)
  point P1 (0, 0)
  point P2 (61.9093, -27.066)
  point P3 (124, 27.066)
  point P4 (124, -27.066)
  dimension "d321" distance P1 P2 = 61.9093 (= "Linear Dimension-2")
  dimension "d322" distance P1 P2 = 27.066 (= "Linear Dimension-3")
  dimension "d323" distance P1 P3 = 124 (= "Linear Dimension-4")
  dimension "d324" distance P1 P3 = 27.066 (= "Linear Dimension-5")
  dimension "d325" distance P1 P4 = 124 (= "Linear Dimension-6")
  dimension "d326" distance P1 P4 = 27.066 (= "Linear Dimension-7")
  dimension "d327" = 4 (= "memberWidth / 2")
extrude "Extrude24" cut sketch "A Facet 315 Triangle 4" profile of L5 L6 L4 against normal blind 4.7 (magnitude of "-( wall + 0.2 mm )")
fillet "Fillet8" radius 1.5 (= "apertureRadius")
work_plane "WorkPlane1" RotateAngle -90 ExtraOffset 0
work_plane "WorkPlane2" AlongDistance 75 (= "bodyWidth / 2") ExtraOffset 0
sketch "B Facet 0 Triangle 1" plane through (0, 75, 0) normal (0, 1, 0) x axis (1, 0, 0)
  line L1 (-84.8995, -27.066) -> (-84.8995, 27.066)
  line L2 (-124, 27.066) -> (-84.8995, -27.066)
  line L3 (-84.8995, 27.066) -> (-124, 27.066)
  line L4 (-88.8995, -14.697) -> (-88.8995, 23.066)
  line L5 (-116.1764, 23.066) -> (-88.8995, -14.697)
  line L6 (-88.8995, 23.066) -> (-116.1764, 23.066)
  point P1 (0, 0)
  point P2 (-84.8995, 27.066)
  point P3 (-84.8995, -27.066)
  point P4 (-124, 27.066)
  dimension "d336" distance P1 P2 = 84.8995 (= "Linear Dimension-2")
  dimension "d337" distance P1 P2 = 27.066 (= "Linear Dimension-3")
  dimension "d338" distance P1 P3 = 84.8995 (= "Linear Dimension-4")
  dimension "d339" distance P1 P3 = 27.066 (= "Linear Dimension-5")
  dimension "d340" distance P1 P4 = 124 (= "Linear Dimension-6")
  dimension "d341" distance P1 P4 = 27.066 (= "Linear Dimension-7")
  dimension "d342" = 4 (= "memberWidth / 2")
extrude "Extrude1" cut sketch "B Facet 0 Triangle 1" profile of L5 L6 L4 against normal blind 4.7 (magnitude of "-( wall + 0.2 mm )")
sketch "B Facet 0 Triangle 2" plane through (0, 75, 0) normal (0, 1, 0) x axis (1, 0, 0)
  line L1 (-124, 27.066) -> (-84.8995, -27.066)
  line L2 (-124, -27.066) -> (-124, 27.066)
  line L3 (-84.8995, -27.066) -> (-124, -27.066)
  line L4 (-120, 14.697) -> (-92.7231, -23.066)
  line L5 (-120, -23.066) -> (-120, 14.697)
  line L6 (-92.7231, -23.066) -> (-120, -23.066)
  point P1 (0, 0)
  point P2 (-84.8995, -27.066)
  point P3 (-124, 27.066)
  point P4 (-124, -27.066)
  dimension "d345" distance P1 P2 = 84.8995 (= "Linear Dimension-2")
  dimension "d346" distance P1 P2 = 27.066 (= "Linear Dimension-3")
  dimension "d347" distance P1 P3 = 124 (= "Linear Dimension-4")
  dimension "d348" distance P1 P3 = 27.066 (= "Linear Dimension-5")
  dimension "d349" distance P1 P4 = 124 (= "Linear Dimension-6")
  dimension "d350" distance P1 P4 = 27.066 (= "Linear Dimension-7")
  dimension "d351" = -4 (= "-memberWidth / 2")
extrude "Extrude2" cut sketch "B Facet 0 Triangle 2" profile of L5 L6 L4 against normal blind 4.7 (magnitude of "-( wall + 0.2 mm )")
fillet "Fillet1" radius 1.5 (= "apertureRadius")
work_plane "WorkPlane3" RotateAngle -45 ExtraOffset 0
work_plane "WorkPlane4" AlongDistance 75 (= "bodyWidth / 2") ExtraOffset 0
sketch "B Facet 45 Triangle 1" plane through (0, 53.033, 53.033) normal (0, 0.7071, 0.7071) x axis (1, 0, 0)
  line L1 (-43.7939, -27.066) -> (-82.0711, 27.066)
  line L2 (-124, 27.066) -> (-43.7939, -27.066)
  line L3 (-82.0711, 27.066) -> (-124, 27.066)
  line L4 (-59.6927, -11.51) -> (-84.1416, 23.066)
  line L5 (-110.9231, 23.066) -> (-59.6927, -11.51)
  line L6 (-84.1416, 23.066) -> (-110.9231, 23.066)
  point P1 (0, 0)
  point P2 (-82.0711, 27.066)
  point P3 (-43.7939, -27.066)
  point P4 (-124, 27.066)
  dimension "d360" distance P1 P2 = 82.0711 (= "Linear Dimension-2")
  dimension "d361" distance P1 P2 = 27.066 (= "Linear Dimension-3")
  dimension "d362" distance P1 P3 = 43.7939 (= "Linear Dimension-4")
  dimension "d363" distance P1 P3 = 27.066 (= "Linear Dimension-5")
  dimension "d364" distance P1 P4 = 124 (= "Linear Dimension-6")
  dimension "d365" distance P1 P4 = 27.066 (= "Linear Dimension-7")
  dimension "d366" = 4 (= "memberWidth / 2")
extrude "Extrude3" cut sketch "B Facet 45 Triangle 1" profile of L5 L6 L4 against normal blind 4.7 (magnitude of "-( wall + 0.2 mm )")
sketch "B Facet 45 Triangle 2" plane through (0, 53.033, 53.033) normal (0, 0.7071, 0.7071) x axis (1, 0, 0)
  line L1 (-124, 27.066) -> (-43.7939, -27.066)
  line L2 (-124, -27.066) -> (-124, 27.066)
  line L3 (-43.7939, -27.066) -> (-124, -27.066)
  line L4 (-120, 19.5406) -> (-56.8709, -23.066)
  line L5 (-120, -23.066) -> (-120, 19.5406)
  line L6 (-56.8709, -23.066) -> (-120, -23.066)
  point P1 (0, 0)
  point P2 (-43.7939, -27.066)
  point P3 (-124, 27.066)
  point P4 (-124, -27.066)
  dimension "d369" distance P1 P2 = 43.7939 (= "Linear Dimension-2")
  dimension "d370" distance P1 P2 = 27.066 (= "Linear Dimension-3")
  dimension "d371" distance P1 P3 = 124 (= "Linear Dimension-4")
  dimension "d372" distance P1 P3 = 27.066 (= "Linear Dimension-5")
  dimension "d373" distance P1 P4 = 124 (= "Linear Dimension-6")
  dimension "d374" distance P1 P4 = 27.066 (= "Linear Dimension-7")
  dimension "d375" = -4 (= "-memberWidth / 2")
extrude "Extrude4" cut sketch "B Facet 45 Triangle 2" profile of L5 L6 L4 against normal blind 4.7 (magnitude of "-( wall + 0.2 mm )")
fillet "Fillet2" radius 1.5 (= "apertureRadius")
work_plane "WorkPlane5" RotateAngle 0 ExtraOffset 0
work_plane "WorkPlane6" AlongDistance 75 (= "bodyWidth / 2") ExtraOffset 0
sketch "B Facet 90 Triangle 1" plane through (0, 0, 75) normal (0, 0, 1) x axis (1, 0, 0)
  line L1 (-36.9655, 27.066) -> (17.1665, -27.066)
  line L2 (-53.4167, -27.066) -> (-36.9655, 27.066)
  line L3 (17.1665, -27.066) -> (-53.4167, -27.066)
  line L4 (-35.0777, 19.5214) -> (7.5097, -23.066)
  line L5 (-48.0205, -23.066) -> (-35.0777, 19.5214)
  line L6 (7.5097, -23.066) -> (-48.0205, -23.066)
  point P1 (0, 0)
  point P2 (17.1665, -27.066)
  point P3 (-36.9655, 27.066)
  point P4 (-53.4167, -27.066)
  dimension "d384" distance P1 P2 = 17.1665 (= "Linear Dimension-2")
  dimension "d385" distance P1 P2 = 27.066 (= "Linear Dimension-3")
  dimension "d386" distance P1 P3 = 36.9655 (= "Linear Dimension-4")
  dimension "d387" distance P1 P3 = 27.066 (= "Linear Dimension-5")
  dimension "d388" distance P1 P4 = 53.4167 (= "Linear Dimension-6")
  dimension "d389" distance P1 P4 = 27.066 (= "Linear Dimension-7")
  dimension "d390" = -4 (= "-memberWidth / 2")
extrude "Extrude5" cut sketch "B Facet 90 Triangle 1" profile of L5 L6 L4 against normal blind 4.7 (magnitude of "-( wall + 0.2 mm )")
sketch "B Facet 90 Triangle 2" plane through (0, 0, 75) normal (0, 0, 1) x axis (1, 0, 0)
  line L1 (-53.4167, -27.066) -> (-36.9655, 27.066)
  line L2 (-124, 27.066) -> (-53.4167, -27.066)
  line L3 (-36.9655, 27.066) -> (-124, 27.066)
  line L4 (-55.5648, -20.3777) -> (-42.3618, 23.066)
  line L5 (-112.2115, 23.066) -> (-55.5648, -20.3777)
  line L6 (-42.3618, 23.066) -> (-112.2115, 23.066)
  point P1 (0, 0)
  point P2 (-36.9655, 27.066)
  point P3 (-53.4167, -27.066)
  point P4 (-124, 27.066)
  dimension "d393" distance P1 P2 = 36.9655 (= "Linear Dimension-2")
  dimension "d394" distance P1 P2 = 27.066 (= "Linear Dimension-3")
  dimension "d395" distance P1 P3 = 53.4167 (= "Linear Dimension-4")
  dimension "d396" distance P1 P3 = 27.066 (= "Linear Dimension-5")
  dimension "d397" distance P1 P4 = 124 (= "Linear Dimension-6")
  dimension "d398" distance P1 P4 = 27.066 (= "Linear Dimension-7")
  dimension "d399" = 4 (= "memberWidth / 2")
extrude "Extrude6" cut sketch "B Facet 90 Triangle 2" profile of L5 L6 L4 against normal blind 4.7 (magnitude of "-( wall + 0.2 mm )")
sketch "B Facet 90 Triangle 3" plane through (0, 0, 75) normal (0, 0, 1) x axis (1, 0, 0)
  line L1 (-124, 27.066) -> (-53.4167, -27.066)
  line L2 (-124, -27.066) -> (-124, 27.066)
  line L3 (-53.4167, -27.066) -> (-124, -27.066)
  line L4 (-120, 18.9574) -> (-65.2053, -23.066)
  line L5 (-120, -23.066) -> (-120, 18.9574)
  line L6 (-65.2053, -23.066) -> (-120, -23.066)
  point P1 (0, 0)
  point P2 (-53.4167, -27.066)
  point P3 (-124, 27.066)
  point P4 (-124, -27.066)
  dimension "d402" distance P1 P2 = 53.4167 (= "Linear Dimension-2")
  dimension "d403" distance P1 P2 = 27.066 (= "Linear Dimension-3")
  dimension "d404" distance P1 P3 = 124 (= "Linear Dimension-4")
  dimension "d405" distance P1 P3 = 27.066 (= "Linear Dimension-5")
  dimension "d406" distance P1 P4 = 124 (= "Linear Dimension-6")
  dimension "d407" distance P1 P4 = 27.066 (= "Linear Dimension-7")
  dimension "d408" = -4 (= "-memberWidth / 2")
extrude "Extrude7" cut sketch "B Facet 90 Triangle 3" profile of L5 L6 L4 against normal blind 4.7 (magnitude of "-( wall + 0.2 mm )")
fillet "Fillet3" radius 1.5 (= "apertureRadius")
work_plane "WorkPlane7" RotateAngle 45 ExtraOffset 0
work_plane "WorkPlane8" AlongDistance 75 (= "bodyWidth / 2") ExtraOffset 0
sketch "B Facet 135 Triangle 1" plane through (0, -53.033, 53.033) normal (0, -0.7071, 0.7071) x axis (1, 0, 0)
  line L1 (62.2721, -27.066) -> (23.9949, 27.066)
  line L2 (-25.3367, 27.066) -> (62.2721, -27.066)
  line L3 (23.9949, 27.066) -> (-25.3367, 27.066)
  line L4 (47.6674, -13.34) -> (21.9244, 23.066)
  line L5 (-11.2532, 23.066) -> (47.6674, -13.34)
  line L6 (21.9244, 23.066) -> (-11.2532, 23.066)
  point P1 (0, 0)
  point P2 (23.9949, 27.066)
  point P3 (62.2721, -27.066)
  point P4 (-25.3367, 27.066)
  dimension "d417" distance P1 P2 = 23.9949 (= "Linear Dimension-2")
  dimension "d418" distance P1 P2 = 27.066 (= "Linear Dimension-3")
  dimension "d419" distance P1 P3 = 62.2721 (= "Linear Dimension-4")
  dimension "d420" distance P1 P3 = 27.066 (= "Linear Dimension-5")
  dimension "d421" distance P1 P4 = 25.3367 (= "Linear Dimension-6")
  dimension "d422" distance P1 P4 = 27.066 (= "Linear Dimension-7")
  dimension "d423" = 4 (= "memberWidth / 2")
extrude "Extrude8" cut sketch "B Facet 135 Triangle 1" profile of L5 L6 L4 against normal blind 4.7 (magnitude of "-( wall + 0.2 mm )")
sketch "B Facet 135 Triangle 2" plane through (0, -53.033, 53.033) normal (0, -0.7071, 0.7071) x axis (1, 0, 0)
  line L1 (-25.3367, 27.066) -> (62.2721, -27.066)
  line L2 (-61.9093, -27.066) -> (-25.3367, 27.066)
  line L3 (62.2721, -27.066) -> (-61.9093, -27.066)
  line L4 (-24.1722, 21.6445) -> (48.1886, -23.066)
  line L5 (-54.3795, -23.066) -> (-24.1722, 21.6445)
  line L6 (48.1886, -23.066) -> (-54.3795, -23.066)
  point P1 (0, 0)
  point P2 (62.2721, -27.066)
  point P3 (-25.3367, 27.066)
  point P4 (-61.9093, -27.066)
  dimension "d426" distance P1 P2 = 62.2721 (= "Linear Dimension-2")
  dimension "d427" distance P1 P2 = 27.066 (= "Linear Dimension-3")
  dimension "d428" distance P1 P3 = 25.3367 (= "Linear Dimension-4")
  dimension "d429" distance P1 P3 = 27.066 (= "Linear Dimension-5")
  dimension "d430" distance P1 P4 = 61.9093 (= "Linear Dimension-6")
  dimension "d431" distance P1 P4 = 27.066 (= "Linear Dimension-7")
  dimension "d432" = -4 (= "-memberWidth / 2")
extrude "Extrude9" cut sketch "B Facet 135 Triangle 2" profile of L5 L6 L4 against normal blind 4.7 (magnitude of "-( wall + 0.2 mm )")
sketch "B Facet 135 Triangle 3" plane through (0, -53.033, 53.033) normal (0, -0.7071, 0.7071) x axis (1, 0, 0)
  line L1 (-61.9093, -27.066) -> (-25.3367, 27.066)
  line L2 (-124, 27.066) -> (-61.9093, -27.066)
  line L3 (-25.3367, 27.066) -> (-124, 27.066)
  line L4 (-62.6909, -21.0779) -> (-32.8665, 23.066)
  line L5 (-113.325, 23.066) -> (-62.6909, -21.0779)
  line L6 (-32.8665, 23.066) -> (-113.325, 23.066)
  point P1 (0, 0)
  point P2 (-25.3367, 27.066)
  point P3 (-61.9093, -27.066)
  point P4 (-124, 27.066)
  dimension "d435" distance P1 P2 = 25.3367 (= "Linear Dimension-2")
  dimension "d436" distance P1 P2 = 27.066 (= "Linear Dimension-3")
  dimension "d437" distance P1 P3 = 61.9093 (= "Linear Dimension-4")
  dimension "d438" distance P1 P3 = 27.066 (= "Linear Dimension-5")
  dimension "d439" distance P1 P4 = 124 (= "Linear Dimension-6")
  dimension "d440" distance P1 P4 = 27.066 (= "Linear Dimension-7")
  dimension "d441" = 4 (= "memberWidth / 2")
extrude "Extrude10" cut sketch "B Facet 135 Triangle 3" profile of L5 L6 L4 against normal blind 4.7 (magnitude of "-( wall + 0.2 mm )")
sketch "B Facet 135 Triangle 4" plane through (0, -53.033, 53.033) normal (0, -0.7071, 0.7071) x axis (1, 0, 0)
  line L1 (-124, 27.066) -> (-61.9093, -27.066)
  line L2 (-124, -27.066) -> (-124, 27.066)
  line L3 (-61.9093, -27.066) -> (-124, -27.066)
  line L4 (-120, 18.272) -> (-72.5843, -23.066)
  line L5 (-120, -23.066) -> (-120, 18.272)
  line L6 (-72.5843, -23.066) -> (-120, -23.066)
  point P1 (0, 0)
  point P2 (-61.9093, -27.066)
  point P3 (-124, 27.066)
  point P4 (-124, -27.066)
  dimension "d444" distance P1 P2 = 61.9093 (= "Linear Dimension-2")
  dimension "d445" distance P1 P2 = 27.066 (= "Linear Dimension-3")
  dimension "d446" distance P1 P3 = 124 (= "Linear Dimension-4")
  dimension "d447" distance P1 P3 = 27.066 (= "Linear Dimension-5")
  dimension "d448" distance P1 P4 = 124 (= "Linear Dimension-6")
  dimension "d449" distance P1 P4 = 27.066 (= "Linear Dimension-7")
  dimension "d450" = -4 (= "-memberWidth / 2")
extrude "Extrude11" cut sketch "B Facet 135 Triangle 4" profile of L5 L6 L4 against normal blind 4.7 (magnitude of "-( wall + 0.2 mm )")
fillet "Fillet4" radius 1.5 (= "apertureRadius")
work_plane "WorkPlane9" RotateAngle 90 ExtraOffset 0
work_plane "WorkPlane10" AlongDistance 75 (= "bodyWidth / 2") ExtraOffset 0
sketch "B Facet 180 Triangle 1" plane through (0, -75, 0) normal (0, -1, 0) x axis (-1, 0, 0)
  line L1 (-65.1005, 27.066) -> (-65.1005, -27.066)
  line L2 (-2.067, -27.066) -> (-65.1005, 27.066)
  line L3 (-65.1005, -27.066) -> (-2.067, -27.066)
  line L4 (-61.1005, 18.3583) -> (-61.1005, -23.066)
  line L5 (-12.8644, -23.066) -> (-61.1005, 18.3583)
  line L6 (-61.1005, -23.066) -> (-12.8644, -23.066)
  point P1 (0, 0)
  point P2 (-65.1005, -27.066)
  point P3 (-65.1005, 27.066)
  point P4 (-2.067, -27.066)
  dimension "d459" distance P1 P2 = 65.1005 (= "Linear Dimension-2")
  dimension "d460" distance P1 P2 = 27.066 (= "Linear Dimension-3")
  dimension "d461" distance P1 P3 = 65.1005 (= "Linear Dimension-4")
  dimension "d462" distance P1 P3 = 27.066 (= "Linear Dimension-5")
  dimension "d463" distance P1 P4 = 2.067 (= "Linear Dimension-6")
  dimension "d464" distance P1 P4 = 27.066 (= "Linear Dimension-7")
  dimension "d465" = 4 (= "memberWidth / 2")
extrude "Extrude12" cut sketch "B Facet 180 Triangle 1" profile of L5 L6 L4 against normal blind 4.7 (magnitude of "-( wall + 0.2 mm )")
sketch "B Facet 180 Triangle 2" plane through (0, -75, 0) normal (0, -1, 0) x axis (-1, 0, 0)
  line L1 (-2.067, -27.066) -> (-65.1005, 27.066)
  line L2 (60.9665, 27.066) -> (-2.067, -27.066)
  line L3 (-65.1005, 27.066) -> (60.9665, 27.066)
  line L4 (-2.067, -21.7934) -> (-54.3031, 23.066)
  line L5 (50.1691, 23.066) -> (-2.067, -21.7934)
  line L6 (-54.3031, 23.066) -> (50.1691, 23.066)
  point P1 (0, 0)
  point P2 (-65.1005, 27.066)
  point P3 (-2.067, -27.066)
  point P4 (60.9665, 27.066)
  dimension "d468" distance P1 P2 = 65.1005 (= "Linear Dimension-2")
  dimension "d469" distance P1 P2 = 27.066 (= "Linear Dimension-3")
  dimension "d470" distance P1 P3 = 2.067 (= "Linear Dimension-4")
  dimension "d471" distance P1 P3 = 27.066 (= "Linear Dimension-5")
  dimension "d472" distance P1 P4 = 60.9665 (= "Linear Dimension-6")
  dimension "d473" distance P1 P4 = 27.066 (= "Linear Dimension-7")
  dimension "d474" = -4 (= "-memberWidth / 2")
extrude "Extrude13" cut sketch "B Facet 180 Triangle 2" profile of L5 L6 L4 against normal blind 4.7 (magnitude of "-( wall + 0.2 mm )")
